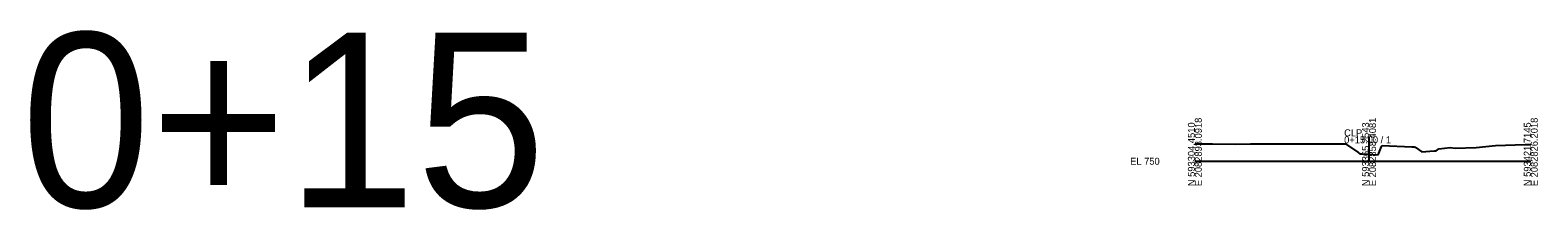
# Model space of a CAD drawing. Extents: x -577 to 1138, y -35 to 4556.
# Drawn here: x -468 to 138, y 1481 to 1553 of the extents above; entities that cross this region are included whole.
import ezdxf

# ---------------------------------------------------------------- set-up
doc = ezdxf.new("R2010")
doc.units = 0
for name, color, linetype in [('GK_Cells', 7, 'Continuous'), ('SC_Scratch1', 7, 'Continuous'), ('XS_X_Ground_Line', 7, 'Continuous')]:
    doc.layers.add(name, color=color, linetype=linetype)

msp = doc.modelspace()

# ---------------------------------------------------------------- linework, layer by layer
at = {"layer": 'GK_Cells'}
for p, q in [((70, 1500), (70, 1510)), ((0, 1500), (70, 1500)), ((70, 1500), (135, 1500))]:
    msp.add_line(p, q, dxfattribs=at)
at = {"layer": 'XS_X_Ground_Line'}
for p, q in [((0, 1507.03), (0.1, 1507.03)), ((0.1, 1507.03), (6.58, 1506.93)), ((6.58, 1506.93), (6.63, 1506.93)), ((6.63, 1506.93), (6.72, 1506.93)), ((6.72, 1506.93), (7.03, 1506.93)), ((7.03, 1506.93), (16.23, 1506.91)), ((16.23, 1506.91), (22.42, 1506.95)), ((22.42, 1506.95), (23.07, 1506.96)), ((23.07, 1506.96), (24.55, 1506.97)), ((24.55, 1506.97), (27.9, 1506.99)), ((27.9, 1506.99), (29.19, 1507)), ((29.19, 1507), (29.64, 1507)), ((29.64, 1507), (30.68, 1507.01)), ((30.68, 1507.01), (31.36, 1507.01)), ((31.36, 1507.01), (38.5, 1506.97)), ((38.5, 1506.97), (39.62, 1506.97)), ((39.62, 1506.97), (40.95, 1506.98)), ((40.95, 1506.98), (41.5, 1506.98)), ((41.5, 1506.98), (42.68, 1506.98)), ((42.68, 1506.98), (44.7, 1506.96)), ((44.7, 1506.96), (45.71, 1506.96)), ((45.71, 1506.96), (46.18, 1506.95)), ((46.18, 1506.95), (47.31, 1506.95)), ((47.31, 1506.95), (48.02, 1506.94)), ((48.02, 1506.94), (60.51, 1507.05)), ((60.51, 1507.05), (65.49, 1503.69)), ((65.49, 1503.69), (65.53, 1503.65)), ((65.53, 1503.65), (65.63, 1503.57)), ((65.63, 1503.57), (65.69, 1503.52)), ((65.69, 1503.52), (66.31, 1503.01)), ((66.31, 1503.01), (66.48, 1503.01)), ((66.48, 1503.01), (67.31, 1503)), ((67.31, 1503), (73.69, 1502.57)), ((73.69, 1502.57), (75.04, 1505.86)), ((75.04, 1505.86), (75.13, 1506.07)), ((75.13, 1506.07), (75.24, 1506.37)), ((75.24, 1506.37), (87.18, 1505.78)), ((87.18, 1505.78), (87.19, 1505.78)), ((87.19, 1505.78), (87.32, 1505.78)), ((87.32, 1505.78), (87.81, 1505.8)), ((87.81, 1505.8), (88.15, 1505.82)), ((88.15, 1505.82), (88.16, 1505.82)), ((88.16, 1505.82), (88.5, 1505.61)), ((88.5, 1505.61), (91.24, 1503.77)), ((91.24, 1503.77), (94.37, 1504.08)), ((94.37, 1504.08), (96.37, 1504.16)), ((96.37, 1504.16), (96.92, 1504.13)), ((96.92, 1504.13), (98.06, 1505)), ((98.06, 1505), (102.61, 1505.48)), ((102.61, 1505.48), (104.59, 1505.24)), ((104.59, 1505.24), (113, 1505.52)), ((113, 1505.52), (120.81, 1506.36)), ((120.81, 1506.36), (132.75, 1506.72)), ((132.75, 1506.72), (135, 1506.79))]:
    msp.add_line(p, q, dxfattribs=at)

# ---------------------------------------------------------------- texts
at = {"layer": 'GK_Cells'}
for s, p in [('N 593304.4510', (0, 1490)), ('E 2082893.0918', (2.8, 1490)), ('N 593365.2543', (70, 1490)), ('E 2082858.4081', (72.8, 1490)), ('N 593421.7145', (135, 1490)), ('E 2082826.2018', (137.8, 1490))]:
    msp.add_text(s, height=2.8, rotation=90, dxfattribs=at).set_placement(p)
for s, p in [('0+15.00 / 1', (60, 1507.2)), ('CLP_', (60, 1510)), ('EL 750', (-26, 1498.6))]:
    msp.add_text(s, height=2.8, dxfattribs=at).set_placement(p)
at = {"layer": 'SC_Scratch1'}
msp.add_text('0+15', height=70, dxfattribs=at).set_placement((-471.72, 1481.53))

doc.saveas('drawing.dxf')
